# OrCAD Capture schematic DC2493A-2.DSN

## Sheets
1 PAGE2: size A
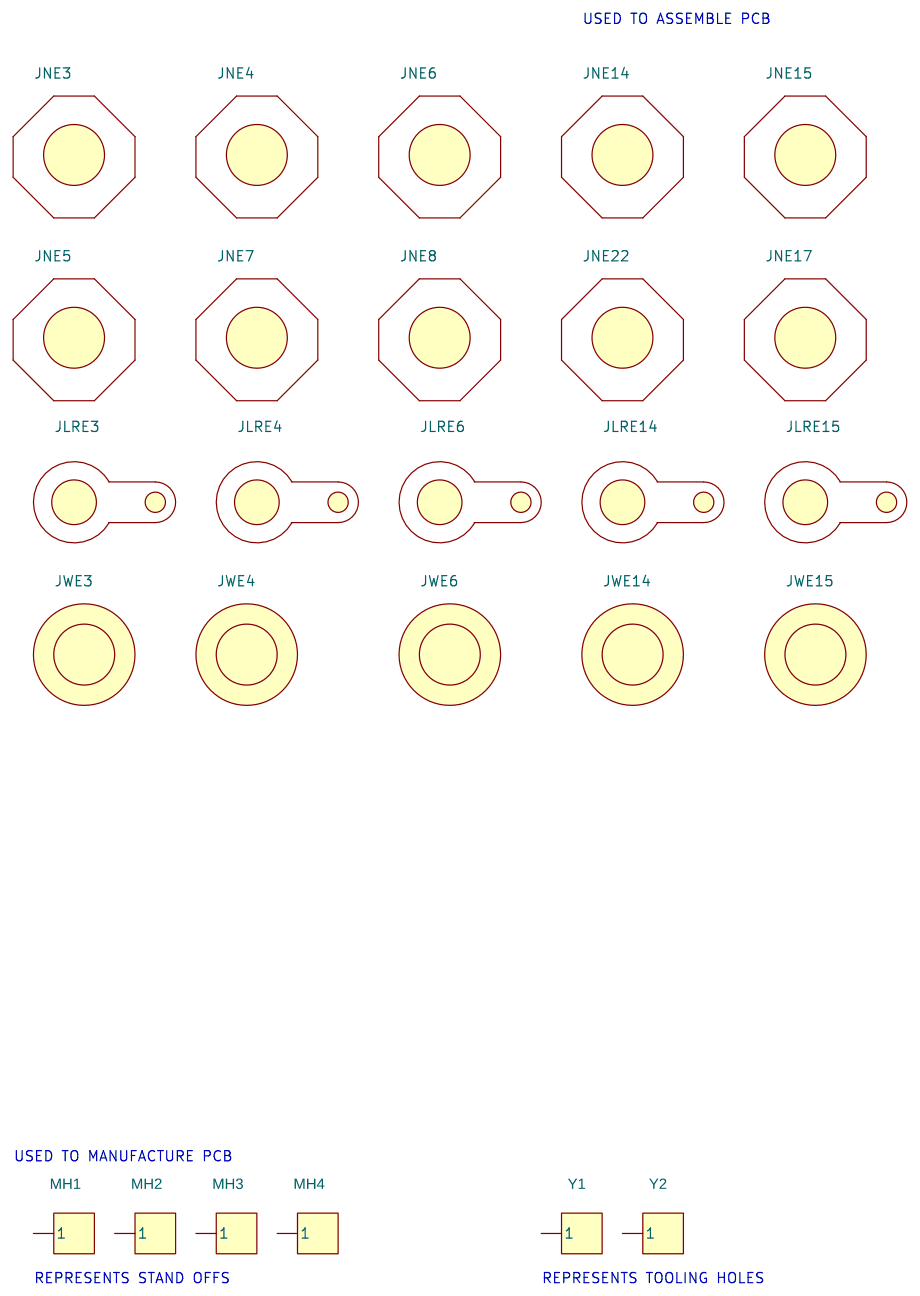
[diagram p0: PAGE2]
2 PAGE1: size Custom; title: HIGH POWER 60V, 2-PHASE SYNCHRONOUS; rev: 2; company: TM; note: STEP-DOWN SUPPLY
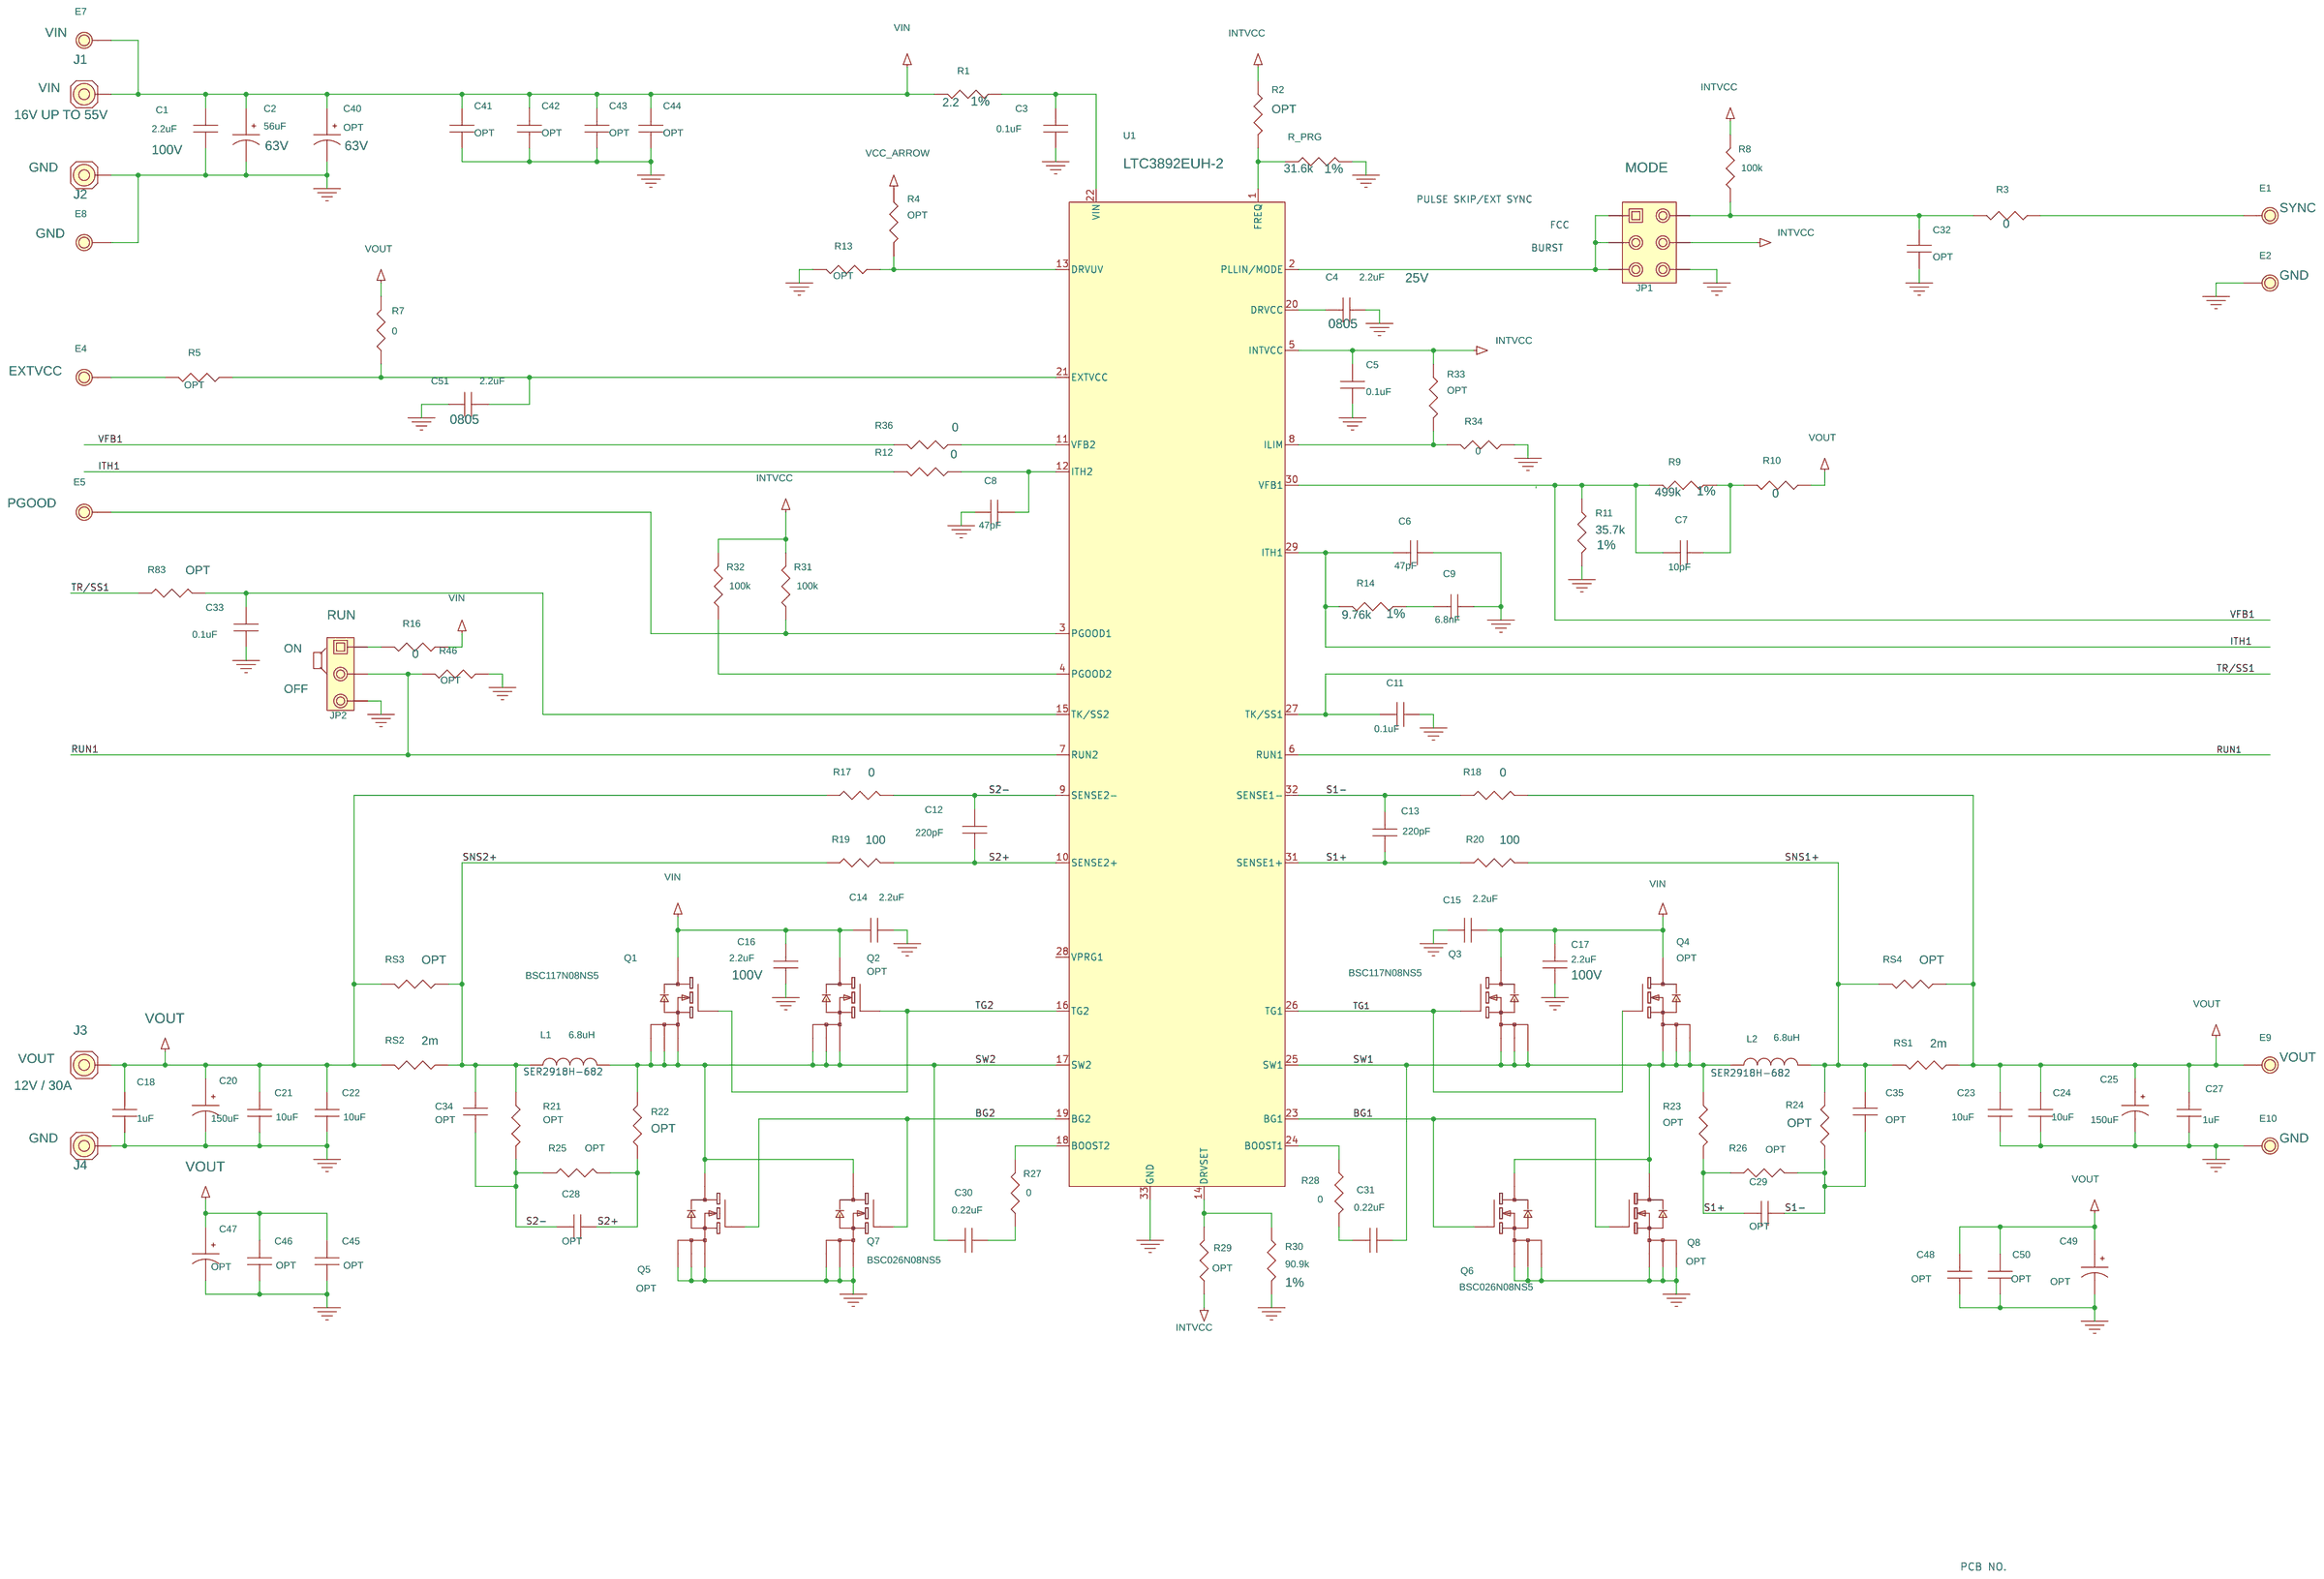
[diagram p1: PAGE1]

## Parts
sheet PAGE1
C1  2.2uF  [1210]
C2  56uF  [CAP\PAN\EEHZA1J560P]
C3  0.1uF  [0805]
C4  2.2uF  [0805]
C5  0.1uF  [0603]
C6  47pF  [0603]
C7  10pF  [0603]
C8  47pF  [0603]
C9  6.8nF  [0603]
C11  0.1uF  [0603]
C12  220pF  [0603]
C13  220pF  [0603]
C14  2.2uF  [1210]
C15  2.2uF  [1210]
C16  2.2uF  [1210]
C17  2.2uF  [1210]
C18  1uF  [0603]
C20  150uF  [CAP\SANYO\SVPA_E7]
C21  10uF  [1206]
C22  10uF  [1206]
C23  10uF  [1206]
C24  10uF  [1206]
C25  150uF  [CAP\SANYO\SVPA_E7]
C27  1uF  [0603]
C28  OPT  [0603]
C29  OPT  [0603]
C30  0.22uF  [0603]
C31  0.22uF  [0603]
C32  OPT  [0603]
C33  0.1uF  [0805]
C34  OPT  [0603]
C35  OPT  [0603]
C40  OPT  [CAP\PAN\EEHZA1J560P]
C41  OPT  [0805]
C42  OPT  [0805]
C43  OPT  [0805]
C44  OPT  [0805]
C45  OPT  [1206]
C46  OPT  [1206]
C47  OPT  [CAP\SANYO\SVPA_E7]
C48  OPT  [1206]
C49  OPT  [CAP\SANYO\SVPA_E7]
C50  OPT  [1206]
C51  2.2uF  [0805]
E1  SYNC  [MM/2501]
E2  GND  [MM/2501]
E4  EXTVCC  [MM/2501]
E5  PGOOD  [MM/2501]
E7  VIN  [MM/2501]
E8  GND  [MM/2501]
E9  VOUT  [MM/2501]
E10  GND  [MM/2501]
J1  Testpin  [con\lug\10]
J2  Testpin  [con\lug\10]
J3  Testpin  [con\lug\10]
J4  Testpin  [con\lug\10]
JP1  2 Pins 2mm Ctrs.  [HDR\3X2\2MM]
JP2  3 Pins 2mm Ctrs.  [commcon2802s03g2]
L1  6.8uH  [IND\CLCRFT\SER2900]
L2  6.8uH  [IND\CLCRFT\SER2900]
Q1  BSC117N08NS5  [LFPAK]
Q2  OPT  [LFPAK]
Q3  BSC117N08NS5  [LFPAK]
Q4  OPT  [LFPAK]
Q5  OPT  [LFPAK]
Q6  BSC026N08NS5  [LFPAK]
Q7  BSC026N08NS5  [LFPAK]
Q8  OPT  [LFPAK]
R1  2.2  [1206]
R2  OPT  [0603]
R3  0  [0603]
R4  OPT  [0603]
R5  OPT  [0603]
R7  0  [0603]
R8  100k  [0603]
R9  499k  [0805]
R10  0  [0603]
R11  35.7k  [0603]
R12  0  [0603]
R13  OPT  [0603]
R14  9.76k  [0603]
R16  0  [0603]
R17  0  [0603]
R18  0  [0603]
R19  100  [0603]
R20  100  [0603]
R21  OPT  [0603]
R22  OPT  [0603]
R23  OPT  [0603]
R24  OPT  [0603]
R25  OPT  [0603]
R26  OPT  [0603]
R27  0  [0603]
R28  0  [0603]
R29  OPT  [0603]
R30  90.9k  [0603]
R31  100k  [0603]
R32  100k  [0603]
R33  OPT  [0603]
R34  0  [0603]
R36  0  [0603]
R46  OPT  [0603]
R83  OPT  [0603]
R_PRG  31.6k  [0603]
RS1  2m  [2010]
RS2  2m  [2010]
RS3  OPT  [2010]
RS4  OPT  [2010]
U1  LTC3892EUH-2  [LT_UH32_5X5]
XJP1  2mm Ctrs.
XJP2  2mm Ctrs.
sheet PAGE2
JLRE3  Lug_Ring
JLRE4  Lug_Ring
JLRE6  Lug_Ring
JLRE14  Lug_Ring
JLRE15  Lug_Ring
JNE3  NUT
JNE4  NUT
JNE5  NUT
JNE6  NUT
JNE7  NUT
JNE8  NUT
JNE14  NUT
JNE15  NUT
JNE17  NUT
JNE22  NUT
JWE3  Washer
JWE4  Washer
JWE6  Washer
JWE14  Washer
JWE15  Washer
MH1  CON1  [KEYSTONE_8831]
MH2  CON1  [KEYSTONE_8831]
MH3  CON1  [KEYSTONE_8831]
MH4  CON1  [KEYSTONE_8831]
Y1  CON1  [TOOL\ALGNHL\70]
Y2  CON1  [TOOL\ALGNHL\70]

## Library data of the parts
C1 C14-C17 = CAP_NP_0: CAP, 1210 2.2uF 10% 100V X7R; Part Number: MURATA GRM32ER72A225KA35; VOLTAGE: 100V
C2 = CAP_POL: CAP, 56uF 20% 63V HYBRID ALUM ELEC; Part Number: PANASONIC EEHZA1J560P; VOLTAGE: 63V
C3 C33 = CAP_NP_0: CAP, 0805 0.1uF 10% 100V X7R; Part Number: MURATA GRM21BR72A104KAC4L; VOLTAGE: 100V
C4 = CAP_NP_0: CAP, 0805 2.2uF 10% 25V X7R; 1PART: 25V; Part Number: MURATA GRM21BR71E225KA73L; VOLTAGE: 25V
C5 = CAP_NP_0: CAP, 0603 0.1uF 10% 50V X7R; Part Number: MURATA GRM188R71H104KA93D; VOLTAGE: 50V
C6 C8 = CAP_NP_0: CAP, 0603 47pF 5% 100V NPO; Part Number: MURATA GRM1885C2A470JA01D; VOLTAGE: 100V
C7 = CAP_NP_0: CAP, 0603 10pF 5% 50V C0G; Part Number: MURATA GRM1885C1H100JA01D; VOLTAGE: ( Opt. )
C9 = CAP_NP_0: CAP, 0603 6.8nF 10% 50V X7R; 1PART: 16V; Part Number: MURATA GRM188R71H682KA01D
C11 = CAP_NP_0: CAP, 0603 0.1uF 10% 100V X7R; Part Number: MURATA GRM188R72A104KA35D; VOLTAGE: 100V
C12 C13 = CAP_NP_0: CAP, 0603 220pF 5% 100V C0G; Part Number: MURATA GRM1885C2A221JA01D; VOLTAGE: 100V
C18 C27 = CAP_NP_0: CAP, 0603 1uF 10% 16V X7R; Part Number: MURATA GRM188R71C105KA12D; VOLTAGE: 16V
C20 = CAP_POL: CAP, 150uF 20% 16V ALUM; MANUFACTURING: 10TPE330M; Part Number: PANASONIC 16SVPC150M; VOLTAGE: 16V
C21-C24 = CAP_NP_0: CAP, 1206 10uF 10% 16V X7R; Part Number: MURATA GRM31CR71C106KAC7L; VOLTAGE: 16V
C25 = CAP_POL: CAP, 150uF 20% 16V ALUM; Part Number: PANASONIC 16SVPC150M
C28 C29 C32 C34 C35 = CAP_NP_0: CAP, 0603 OPTION; Part Number: OPTION; VOLTAGE: ( Opt. )
C30 C31 = CAP_NP_0: CAP, 0603 0.22uF 10% 25V X5R; Part Number: MURATA GRM188R61E224KA88D; VOLTAGE: 25V
C40 = CAP_POL: CAP, 56uF 20% 63V HYBRID ALUM ELEC OPTION; MANUFACTURING: 10TPE330M; Part Number: PANASONIC EEHZA1J560P OPTION; VOLTAGE: 63V
C41-C44 = CAP_NP_0: CAP, 0805 0.1uF 10% 100V X7R OPTION; Part Number: MURATA GRM21BR72A104KAC4L OPTION; VOLTAGE: 100V
C45 C46 C48 C50 = CAP_NP_0: CAP, 1206 10uF 10% 16V X7R OPTION; Part Number: MURATA GRM31CR71C106KAC7L OPTION; VOLTAGE: 16V
C47 C49 = CAP_POL: CAP, 150uF 20% 16V ALUM OPTION; MANUFACTURING: 10TPE330M; Part Number: PANASONIC 16SVPC150M OPTION; VOLTAGE: 16V
C51 = CAP_NP_0: CAP, 0805 2.2uF 10% 25V X7R; Part Number: MURATA GRM21BR71E225KA73L; VOLTAGE: 25V
E1 E2 E4 E5 E7-E10 = MillMax-2501: TURRET; Part Number: MIIL-MAX 2501-2-00-80-00-00-07-0
J1 = PEM-kfh-032-10: STUD, TESTPIN; 10th Part Field: 16V UP TO 55V; 9th Part Field: VIN; Part Number: PEM KFH-032-10
J2 J4 = PEM-kfh-032-10: STUD, TESTPIN; 10th Part Field: 5 - 24V #; 9th Part Field: GND; Part Number: PEM KFH-032-10
J3 = PEM-kfh-032-10: STUD, TESTPIN; 10th Part Field: 12V / 30A; 9th Part Field: VOUT; Part Number: PEM KFH-032-10
JP1 = Samtec_TMM-_0: HEADER, 3PIN, DBL ROW 2mm; 4th Part Field: BURST; 5th Part Field: FCC; 7th Part Field: SYNC; 9th Part Field: MODE; Part Number: SULLINS, NRPN032PAEN-RC
JP2 = Samtec_TMM-103-02-L-S: HEADER, 2mm, 3PIN; 11th Part Field: OFF; 12th Part Field: RUN; 9th Part Field: ON; Part Number: SULLINS, NRPN031PAEN-RC
L1 L2 = INDUCTOR: IND, 6.8uH; Part Number: COILCRAFT SER2918H-682KL
Q1 Q3 = 2N7002_28: XSTR,  MOSFET N-CH 80V 49A TDSON-8; Part Number: INFINEON BSC117N08NS5
Q2 Q4 Q5 Q8 = 2N7002_28: XSTR, OPTION; Part Number: OPTION
Q6 Q7 = 2N7002_28: XSTR,  MOSFET N-CH 80V 100A TDSON-8; Part Number: INFINEON BSC026N08NS5
R1 = R_1: RES. 1206 2.2 OHMS 1% 1/4W; %: 1%; Part Number: VISHAY CRCW12062R20FKEA
R2 R5 R13 R21-R26 R29 R46 R83 = R_1: RES, 0603 OPTION; %: 0.1%; Part Number: OPTION
R3 R7 R12 R16-R18 R34 R36 = R_1: RES, 0603 0 OHM JUMPER; %: 0.1%; Part Number: VISHAY CRCW06030000Z0EA
R4 R33 = R_1: RES, 0603 OPTION; %: 0.1%; Part Number: OPTION; Tol: 1%
R8 R31 R32 = R_1: RES, 0603 100k OHMS 5% 1/10W; %: 1%; Part Number: VISHAY CRCW0603100KJNEA
R9 = R_1: RES, 0805 499k OHMS 1% 1/8W; %: 1%; Part Number: VISHAY, CRCW0805499KFKEA
R10 R27 R28 = R_1: RES, 0603 0 OHM JUMPER; %: 1%; Part Number: VISHAY CRCW06030000Z0EA
R11 = R_1: RES, 0603 35.7k OHMS 1% 1/10W; %: 1%; Part Number: VISHAY CRCW060335K7FKEA
R14 = R_1: RES, 0603 9.76k OHMS 1% 1/10W; %: 1%; Part Number: VISHAY CRCW06039K76FKEA
R19 R20 = R_1: RES, 0603 100 OHMS 5% 1/10W; %: 0.1%; Part Number: VISHAY, CRCW0603100RJNEA
R30 = R_1: RES, 0603 90.9k OHMS 1% 1/10W; %: 1%; Part Number: VISHAY CRCW060390K9FKEA
R_PRG = R_1: RES, 0603 31.6k OHMS 1% 1/10W; %: 1%; Part Number: VISHAY CRCW060331K6FKEA
RS1 RS2 = R_1: RES, 2010 0.002 OHM 1% 1W; %: 1%; Part Number: VISHAY WSL20102L000FEA18
RS3 RS4 = R_1: RES, 2010 OPTION; %: 0.1%; Part Number: OPTION
U1 = LTC3892EUH-2: IC, DUAL OUTPUT HIGH VOLTAGE STEP-DOWN CONVERTER; Part Number: LINEAR TECH. LTC3892EUH-2#PBF
XJP1 = Samtec_2SN-BK-G_0: SHUNT, 2mm; Part Number: SAMTEC 2SN-BK-G
XJP2 = Samtec_2SN-BK-G: SHUNT, 2mm; Part Number: SAMTEC 2SN-BK-G
JLRE3 JLRE4 JLRE6 JLRE14 JLRE15 = Lug_Ring: LUG RING, #10; Part Number: KEYSTONE 8205
JNE3-JNE8 JNE14 JNE15 JNE17 JNE22 = NUT: NUT, BRASS 10-32; Part Number: ANY #10-32
JWE3 JWE4 JWE6 JWE14 JWE15 = Washer: WASHER, #10 TIN PLATED BRASS; Part Number: ANY #10 EXT BZ TN
MH1-MH4 = CON1: STANDOFF, SNAP ON; Part Number: KEYSTONE 8834
Y1 Y2 = CON1: DO NOT STUFF; Part Number: PADS ONLY

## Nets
GND: C1.1 C2.2 C3.1 C4.1 C5.1 C6.1 C8.1 C9.1 C11.1 C14.1 C15.2 C16.1 C17.1 C18.1 C20.2 C21.1 C22.1 C23.1 C24.1 C25.2 C27.1 C32.2 C33.1 C40.2 C41.1 C42.1 C43.1 C44.1 C45.1 C46.1 C47.2 C48.1 C49.2 C50.1 C51.1 E2.1 E8.1 E10.1 J2.1 J4.1 JP1.6 JP2.3 Q5.1 Q5.2 Q5.3 Q6.1 Q6.2 Q6.3 Q7.1 Q7.2 Q7.3 Q8.1 Q8.2 Q8.3 R11.1 R13.1 R30.2 R34.1 R46.1 R_PRG.2 U1.33(GND)
VIN: C1.2 C2.1 C14.2 C15.1 C16.2 C17.2 C40.1 C41.2 C42.2 C43.2 C44.2 E7.1 J1.1 Q1.5 Q2.5 Q3.5 Q4.5 R1.2 R16.2
BG1: Q6.4 Q8.4 U1.23(BG1)
BG2: Q5.4 Q7.4 U1.19(BG2)
INTVCC: C5.2 JP1.4 R2.1 R4.1 R8.2 R29.2 R31.2 R32.2 R33.1 U1.5(INTVCC)
ITH1: C6.2 R12.2 R14.1 U1.29(ITH1)
RUN1: JP2.2 R46.2 U1.6(RUN1) U1.7(RUN2)
S1+: C13.1 C29.2 R20.1 R23.2 R26.1 U1.31(SENSE1+)
S1-: C13.2 C29.1 C35.2 R18.1 R24.1 R26.2 U1.32(SENSE1-)
S2+: C12.1 C28.1 R19.2 R22.1 R25.2 U1.10(SENSE2+)
S2-: C12.2 C28.2 C34.2 R17.2 R21.2 R25.1 U1.9(SENSE2-)
SNS1+: C35.1 L2.2 R20.2 R24.2 RS1.2 RS4.2
SNS2+: C34.1 L1.1 R19.1 R21.1 RS2.1 RS3.1
SW1: C31.1 L2.1 Q3.1 Q3.2 Q3.3 Q4.1 Q4.2 Q4.3 Q6.5 Q8.5 R23.1 U1.25(SW1)
SW2: C30.2 L1.2 Q1.1 Q1.2 Q1.3 Q2.1 Q2.2 Q2.3 Q5.5 Q7.5 R22.2 U1.17(SW2)
TG1: Q3.4 Q4.4 U1.26(TG1)
TG2: Q1.4 Q2.4 U1.16(TG2)
TR/SS1: C11.2 R83.2 U1.27(TK/SS1)
VFB1: C7.2 R9.1 R11.2 R36.2 U1.30(VFB1)
VOUT: C18.2 C20.1 C21.2 C22.2 C23.2 C24.2 C25.1 C27.2 C45.2 C46.2 C47.1 C48.2 C49.1 C50.2 E9.1 J3.1 R7.2 R10.2 R17.1 R18.2 RS1.1 RS2.2 RS3.2 RS4.1
N16718537: C51.2 R5.2 R7.1 U1.21(EXTVCC)
N16723286: C30.1 R27.1
N16832061: R2.2 R_PRG.1 U1.1(FREQ)
N16881627: R27.2 U1.18(BOOST2)
N16882661: R28.1 U1.24(BOOST1)
N16882704: C31.2 R28.2
N16903338: C3.2 R1.1 U1.22(VIN)
N16908653: C32.1 JP1.2 R3.1 R8.1
N16910782: JP1.1 JP1.3 JP1.5 U1.2(PLLIN/MODE)
N16952646: C8.2 R12.1 U1.12(ITH2)
N16974141: R29.1 R30.1 U1.14(DRVSET)
N17026071: C7.1 R9.2 R10.1
N17057940: C9.2 R14.2
N17727374: R36.1 U1.11(VFB2)
N17728175: C33.2 R83.1 U1.15(TK/SS2)
N19575268: E4.1 R5.1
N19576928: JP2.1 R16.1
N19579263: E1.1 R3.2
N19590079: C4.2 U1.20(DRVCC)
N19592782: E5.1 R31.1 U1.3(PGOOD1)
N19592824: R32.1 U1.4(PGOOD2)
N19594434: R33.2 R34.2 U1.8(ILIM)
N19598042: R4.2 R13.2 U1.13(DRVUV)

Not connected (* = marked no-connect by the designer): MH1 1; MH2 1; MH3 1; MH4 1; U1 28(VPRG1); Y1 1; Y2 1

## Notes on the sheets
sheet 1
- USED TO ASSEMBLE PCB
- USED TO MANUFACTURE PCB
- REPRESENTS STAND OFFS
- REPRESENTS TOOLING HOLES
sheet 2
- PULSE SKIP/EXT SYNC
- FCC
- BURST
- SER2918H-682
- SER2918H-682
- PCB NO.
